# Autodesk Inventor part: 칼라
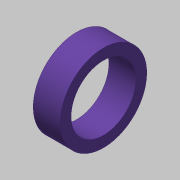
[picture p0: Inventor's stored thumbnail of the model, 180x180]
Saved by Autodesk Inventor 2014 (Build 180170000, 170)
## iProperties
Created: 2020-04
Part Number: 칼라
Material: 강철, 연강
Document SubType Name: Modeling
Designer: mduedu
Density: 7.86 g/cm^3
Appearance: Violet
Mass: 3.45701 g
Surface Area: 6.15752 cm^2
Volume: 0.439823 cm^3
Author: mduedu
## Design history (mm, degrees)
sketch "스케치1"
  geometry: C1 r 8 at (0, 0); C2 r 6 at (0, 0); 1 further point
  constraints: 2 centre point, 2 coincident
  dimensions: "d0" = 16 diameter of C1; "d1" = 12 diameter of C2
extrude "돌출1" new body sketch "스케치1" distance "d2" = 5; taper "d3" = 0 deg
node "솔리드1"
